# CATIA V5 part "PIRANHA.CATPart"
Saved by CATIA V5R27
Part number: PIRANHA
Source: Unknown
Description: Machined Part  
Bounding box of the stored display mesh (mm): x -105 to 305, y -100.193 to 108.038, z 0 to 50
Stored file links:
  H:\STEP-Test-cases\public\installation-with-fasteners\tc4-assembly-PAG\PIRANHA.CATPart
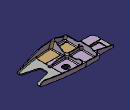
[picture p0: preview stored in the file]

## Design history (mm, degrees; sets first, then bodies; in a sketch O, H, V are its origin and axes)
AxisSystem1: origin (0, 0, 0), X (1, 0, 0), Y (0, 1, 0), Z (0, 0, 1)
Body1 (main body)
  Solid1 "PartBody": solid without history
